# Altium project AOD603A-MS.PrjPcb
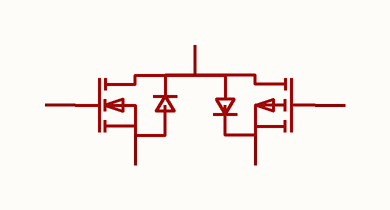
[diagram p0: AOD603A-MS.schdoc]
1 sheet, 1 parts. Net scope: global (net labels, ports and power ports of the same name join across sheets).

## Sheet AOD603A-MS.schdoc
size 127 x 101 mm

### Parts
Q?  aod603a-ms  [TO-252-4_L6.5-W6.1-P1.27-LS9.5-BL]  (value not drawn)

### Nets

Not connected (* = marked no-connect by the designer): Q? 1(S1) 2(G1) 3(D1/D2) 4(S2) 5(G2)

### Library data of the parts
Q? = aod603a-ms: 漏源电压(Vdss):60V;连续漏极电流(Id):13A;导通电阻(RDS(on)):60mΩ@10V;耗散功率(Pd):20W;阈值电压(Vgs(th)):2.5V@250uA;; Manufacturer: MSKSEMI(美森科); AddInBom: yes; ModelId: f7ef85bd5d274b098875077b5a2fb7fc; ModelName: TO-252-4-4P_L6.6-W5.6-H2.3-LS9.8-P1.27; ModelTransform: 259.842,386.37525,0,0,0,0,0,31.496,0; Drain to Source Voltage: 60V; Current - Continuous Drain(Id): 13A; Pd - Power Dissipation: 20W; Gate Charge(Qg): 16.6nC@10V; Input Capacitance(Ciss): 1.18nF; Reverse Transfer Capacitance (Crss@Vds): 45pF; Type: N沟道+P沟道; Output Capacitance(Coss): 68pF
